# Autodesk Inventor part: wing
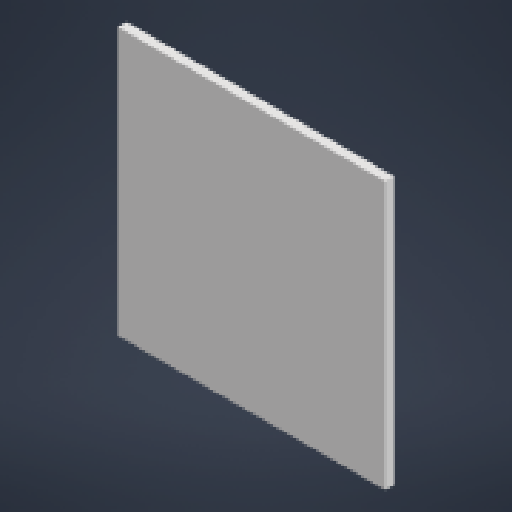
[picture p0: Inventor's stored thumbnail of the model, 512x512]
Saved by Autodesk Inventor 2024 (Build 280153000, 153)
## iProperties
Created: 2023-09
Part Number: wing
Material: Generic
Document SubType Name: Modeling
Designer: mammothbane
Density: 1 g/cm^3
Appearance: Default
Author: mammothbane
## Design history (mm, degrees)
sketch "Sketch1"
  geometry: L1 (-150, 150)-(150, 150); L2 (150, 150)-(150, -150); L3 (150, -150)-(-150, -150); L4 (-150, -150)-(-150, 150); L5 (-150, 150)-(150, -150); L6 (150, 150)-(-150, -150); 1 further point
  constraints: 12 end point, 2 midpoint, 2 parallel, 1 horizontal, 1 perpendicular
  dimensions: "d0" = 300 distance of L2.end L3.end; "d1" = 300 distance of L1.end L2.end
extrude "Extrusion1" new body sketch "Sketch1" distance "d2" = 10; taper "d3" = 0 deg
body "Solid1"
